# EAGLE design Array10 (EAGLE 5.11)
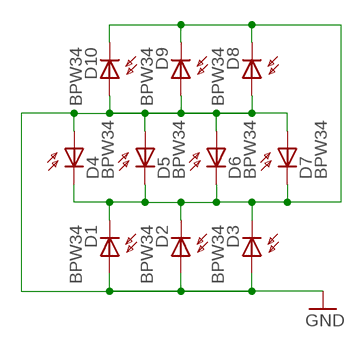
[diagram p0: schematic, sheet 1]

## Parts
D1  BPW34  [BPW34]
D2  BPW34  [BPW34]
D3  BPW34  [BPW34]
D4  BPW34  [BPW34]
D5  BPW34  [BPW34]
D6  BPW34  [BPW34]
D7  BPW34  [BPW34]
D8  BPW34  [BPW34]
D9  BPW34  [BPW34]
D10  BPW34  [BPW34]

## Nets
GND: D1.A D2.A D3.A D4.A D5.A D6.A D7.A D8.A D9.A D10.A
N$4: D1.K(C) D2.K(C) D3.K(C) D4.K(C) D5.K(C) D6.K(C) D7.K(C) D8.K(C) D9.K(C) D10.K(C)

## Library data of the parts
D1-D10 = 00-LIVIO:BPW34: PHOTO DIODE

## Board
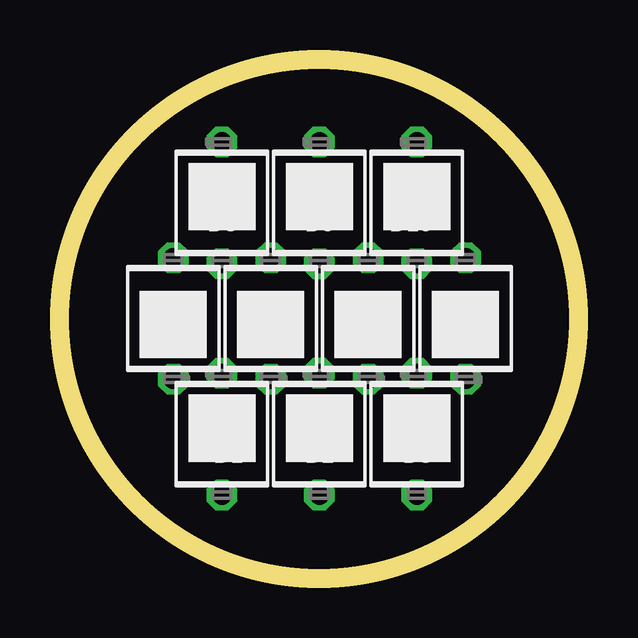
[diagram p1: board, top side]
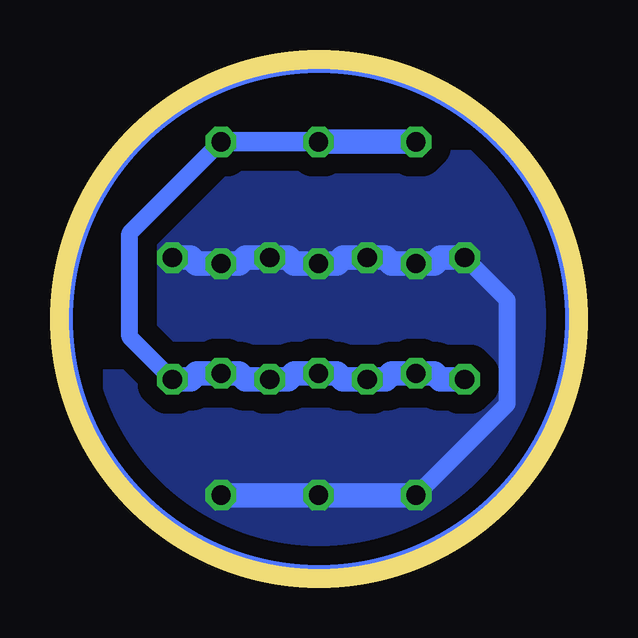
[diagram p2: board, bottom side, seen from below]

Size 21.6 x 21.6 mm. Coordinates in mm from the lower left corner, seen from the top.
Outline: circle at 10.8,10.8 radius 10.8
Copper layers (1*16): Top 0.035mm / dielectric 1.5mm / Bottom 0.035mm
Design rules "FastGcode-DesignRules": minimum track width 10mil, minimum drill 27mil, track to track 27mil, track to pad 27mil, pad to pad 27mil, via to via 27mil, smd to smd 27mil, copper to edge 27mil, drill to drill 8mil, minimum pad ring 5mil, minimum via ring 8mil, stop-mask expansion 4mil, vias tented up to drill 0mil, thermal gap 41mil

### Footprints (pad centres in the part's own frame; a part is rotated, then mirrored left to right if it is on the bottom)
BPW34 = drill 0.8 pad 1.27 octagon: A 0,2.54; K 0,-2.54

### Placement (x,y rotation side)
D1  6.75,5.99 180 top
D2  10.82,5.99 180 top
D3  14.88,5.99 180 top
D4  4.72,10.82 0 top
D5  8.79,10.82 0 top
D6  12.85,10.82 0 top
D7  16.91,10.82 0 top
D8  6.75,15.64 180 top
D9  10.82,15.64 180 top
D10  14.88,15.64 180 top

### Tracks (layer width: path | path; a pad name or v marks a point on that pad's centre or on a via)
GND
  Bottom 0.7: D1.A 2.95,7.26 2.95,11.58 D4.A
  Bottom 1.016: D7.A 16.15,13.36 15.9,13.11 D10.A 14.12,13.11 13.87,13.36 D6.A 12.09,13.36 11.84,13.11 D9.A 10.06,13.11 9.8,13.36 D5.A 8.03,13.36 7.77,13.11 D8.A 5.99,13.11 5.74,13.36 D4.A | D3.A D2.A D1.A
  pour Bottom (isolate 0.8, no thermals): -0.8,-0.8 22.4,-0.8 22.4,22.4 -0.8,22.4
N$4
  Bottom 0.7: D7.K 18.69,10.06 18.69,14.38 D10.K
  Bottom 0.813: D10.K D9.K
  Bottom 1.016: D9.K D8.K | D4.K 5.74,8.28 5.99,8.53 D1.K 7.77,8.53 8.03,8.28 D5.K | D7.K 16.15,8.28 15.9,8.53 D3.K 14.12,8.53 13.87,8.28 D6.K 12.09,8.28 11.84,8.53 D2.K 10.06,8.53 9.8,8.28 D5.K | D5.K 8.53,8.28
(copper drawn outside any net)
  shapes: Bottom circle x1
